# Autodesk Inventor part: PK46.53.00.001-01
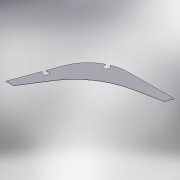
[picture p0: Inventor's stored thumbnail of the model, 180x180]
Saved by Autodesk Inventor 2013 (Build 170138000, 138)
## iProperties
Created: 2005-03
Part Number: PK46.53.00.001-01
Material: Steel, Mild
Document SubType Name: Modeling
Designer: HKostja
Manufacturer: Standard
Standards Organization: Custom
Density: 7.86 g/cm^3
Mass: 4751.84 g
Surface Area: 3132.04 cm^2
Volume: 604.56 cm^3
Author: HKostja
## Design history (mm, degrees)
sketch "Эскиз1"
  geometry: L1 (264.331, 0)-(690, 0); L2 (690, 0)-(665.652, -65.629); L3 (-170, -646.916)-(-240, -646.916); L4 (-240, -646.916)-(-91.941, -247.826); L5 (-170, -646.916)-(-32.608, -429.61); L6 (414.127, -118.858)-(665.652, -65.629); L7 (0, 0)-(559.054, -803.691); L8 (-148.869, -401.272)-(-144.181, -403.012); L9 (-137.737, -371.269)-(-133.05, -373.008); L10 (89.677, -42.515)-(91.976, -46.956); L11 (119.608, -28.638)-(121.512, -33.261); L12 (89.677, -42.515)-(104.341, -34.926); L13 (119.608, -28.638)-(104.341, -34.926); L14 (103.508, -35.71)-(103.28, -35.269); L15 (-143.908, -386.046)-(-143.303, -386.271); A1 r 380 centre (264.331, -380) between (264.331, 0) and (-91.941, -247.826); A2 r 25.5 centre (-120, -394.916) between (-144.181, -403.012) and (-133.05, -373.008); A3 r 25.5 centre (115, -57.916) between (91.976, -46.956) and (121.512, -33.261); A4 r 700 centre (559.054, -803.691) between (414.127, -118.858) and (-32.608, -429.61); 1 further point
  constraints: 30 end point, 13 point on circle, 11 point on line, 6 tangent, 5 parallel, 4 centre point, 4 equal length, 3 perpendicular, 1 coincident, 1 equal radius, 1 horizontal, 1 other
  dimensions: "d0" = 690 distance of L7.start L1.end; "d1" = 70 distance of L3.start L3.end; "d3" = 240 horizontal distance of L7.start L3.end; "d6" = 380 radius of A1; "d9" = 252 distance from line of A2.centre L3; "d10" = 120 horizontal distance of A2.centre L3.end; "d11" = 51 diameter of A2; "d12" = 589 distance from line of A3.centre L3; "d13" = 355 horizontal distance of A3.centre L3.end; "d15" = 700 radius of A4; "d16" = 180 distance from line of L1 point (125.21, -180); "d17" = 5 distance of L10.start L10.end; "d18" = 5 distance of L11.start L11.end (= d17); "d22" = 0.49637 distance of L14.start L14.end (derived); "d23" = 0.64509 distance of L15.start L15.end (derived)
extrude "Выдавливание1" new body sketch "Эскиз1" distance "d7" = 4; taper "d8" = 0 deg
body "Solid1"
